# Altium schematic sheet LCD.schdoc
size 155 x 154 mm
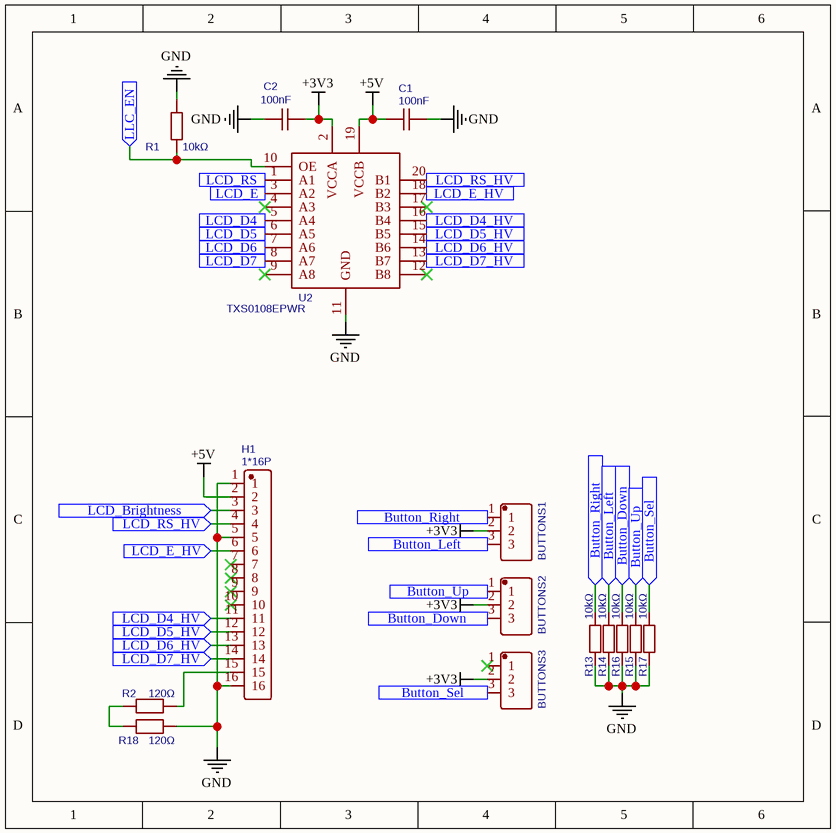
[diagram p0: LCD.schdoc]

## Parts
BUTTONS1  WJ15EDGRC-3.81-3P  [CONN-TH_3P-P3.81_WJ15EDGRC-3.81-3P]  (value not drawn)
BUTTONS2  WJ15EDGRC-3.81-3P  [CONN-TH_3P-P3.81_WJ15EDGRC-3.81-3P]  (value not drawn)
BUTTONS3  WJ15EDGRC-3.81-3P  [CONN-TH_3P-P3.81_WJ15EDGRC-3.81-3P]  (value not drawn)
C1  100nF  [C0603]
C2  100nF  [C0603]
H1  1*16P  [HDR-TH_16P-P2.54-V-M]
R1  10kΩ  [R0603]
R2  120Ω  [R0603]
R13  10kΩ  [R0603]
R14  10kΩ  [R0603]
R15  10kΩ  [R0603]
R16  10kΩ  [R0603]
R17  10kΩ  [R0603]
R18  120Ω  [R0603]
U2  TXS0108EPWR  [TSSOP-20_L6.5-W4.4-P0.65-LS6.4-BL]

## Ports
Button_Down (in), Button_Left (in), Button_Right (in), Button_Sel (in), Button_Up (in), LCD_Brightness (in), LCD_D4 (in), LCD_D4_HV (in), LCD_D5 (in), LCD_D5_HV (in), LCD_D6 (in), LCD_D6_HV (in), LCD_D7 (in), LCD_D7_HV (in), LCD_E (in), LCD_E_HV (in), LCD_RS (in), LCD_RS_HV (in), LLC_EN (in)

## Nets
+3V3: BUTTONS1.2 BUTTONS2.2 BUTTONS3.2 C2.1 U2.2(VCCA)
+5V: C1.1 H1.2 U2.19(VCCB)
GND: C1.2 C2.2 H1.1 H1.5 H1.16 R1.2 R13.1 R14.1 R15.1 R16.1 R17.1 R18.1 U2.11(GND)
Button_Down: BUTTONS2.3 R16.2 ; port Button_Down
Button_Left: BUTTONS1.3 R14.2 ; port Button_Left
Button_Right: BUTTONS1.1 R13.2 ; port Button_Right
Button_Sel: BUTTONS3.3 R17.2 ; port Button_Sel
Button_Up: BUTTONS2.1 R15.2 ; port Button_Up
LCD_Brightness: H1.3 ; port LCD_Brightness
LCD_D4: U2.5(A4) ; port LCD_D4
LCD_D4_HV: H1.11 U2.16(B4) ; port LCD_D4_HV
LCD_D5: U2.6(A5) ; port LCD_D5
LCD_D5_HV: H1.12 U2.15(B5) ; port LCD_D5_HV
LCD_D6: U2.7(A6) ; port LCD_D6
LCD_D6_HV: H1.13 U2.14(B6) ; port LCD_D6_HV
LCD_D7: U2.8(A7) ; port LCD_D7
LCD_D7_HV: H1.14 U2.13(B7) ; port LCD_D7_HV
LCD_E: U2.3(A2) ; port LCD_E
LCD_E_HV: H1.6 U2.18(B2) ; port LCD_E_HV
LCD_RS: U2.1(A1) ; port LCD_RS
LCD_RS_HV: H1.4 U2.20(B1) ; port LCD_RS_HV
LLC_EN: R1.1 U2.10(OE) ; port LLC_EN
NetH1_15: H1.15 R2.1
NetR2_2: R2.2 R18.2

Not connected (* = marked no-connect by the designer): BUTTONS3 1*; H1 7* 8* 9* 10*; U2 4(A3)* 9(A8)* 12(B8)* 17(B3)*

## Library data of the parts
BUTTONS1-BUTTONS3 = WJ15EDGRC-3.81-3P: BOM_Manufacturer: ReliaPro
C1 C2 = 100nF: BOM_Manufacturer: Prosperity Dielectrics; BOM_Manufacturer Part: FN18X104K500PBG; nameAlias: Capacitance; Contributor: LCSC
H1 = 1*16P: BOM_Manufacturer: XKB Connectivity; BOM_Manufacturer Part: X6511WV-16H-C30D60; Contributor: LCSC
R1 R13-R17 = 10kΩ: BOM_Manufacturer: PANASONIC; BOM_Manufacturer Part: ERJ3GEYJ103V; Resistance (Ohms): 10K; nameAlias: Resistance; Contributor: LCSC
R2 R18 = 120Ω: BOM_Manufacturer: PANASONIC; BOM_Manufacturer Part: ERJPA3J121V; Contributor: LCSC; nameAlias: Resistance
U2 = TXS0108EPWR: BOM_Manufacturer: TI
